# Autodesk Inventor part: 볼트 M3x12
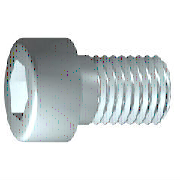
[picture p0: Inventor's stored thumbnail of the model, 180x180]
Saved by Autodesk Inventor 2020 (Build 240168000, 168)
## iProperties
Created: 2012-02
Part Number: 볼트 M3x12
Material: 강철, 연강
Description: 6각머리 태핑 나사
Document SubType Name: Modeling
Standard: KS B 1003
Designer: mduedu
Standards Organization: KS
Language: ko-KR
Size Designation: M 3 x 12
Categories: <MemberInstance><Categories><Category DisplayName="조임쇠" InternalName="e4da775c-781d-43d5-af7c-5136215cf5a6" Mnemonic="FSTN"><Category DisplayName="볼트" InternalN
Density: 1 g/cm^3
Appearance: 강철
IsCustomPart: 0
Author: mduedu
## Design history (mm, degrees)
sketch "스케치1"
  geometry: L1 (-0.867, 0)-(12, 0); L2 (12, 0)-(12, 1.5); L3 (12, 1.5)-(1.25, 1.5); L4 (1.25, 1.5)-(0.943, 1.5); L5 (0.943, 1.5)-(0, 1.5); L6 (0, 1.5)-(0, 2.75); L7 (0, 2.75)-(-3, 2.75); L8 (-3, 2.75)-(-3, 1.443); L9 (-3, 1.443)-(-1.7, 1.443); L10 (-1.7, 1.443)-(-0.867, 0); L11 (-6, 0)-(15, 0) reference; L12 (0, -0.55)-(0, 3.3) reference; L13 (1.25, 1.5)-(0, 1.5)
  constraints: 22 end point, 6 parallel, 2 collinear, 2 perpendicular, 1 horizontal, 1 point on line
  dimensions: "d1" = 10.75 distance from line of L3.end L2 (= GEL); "d2" = 0.30683 distance of L4.end L3.end (computed from GAL); "d3" = 3 distance between parallel lines of L8 L6 (= KOH); "d4" = 1.3 distance of L8.end L9.end (= INTI); "d5" = 60 deg angle of L10 L1; "d6" = 3 diameter of L3 L1 (= GD); "d7" = 3 diameter of L5 L1 (= BDM); "d8" = 2.88675 diameter of L9 L1 (= 1.1547 x SW); "d9" = 5.5 diameter of L7 L1 (= KOD); "d26" = 12 distance between parallel lines of L12 L2 (= NLG)
revolve "본체" sketch "스케치1" stored, may be unused: angle "d10" = 90 deg
sketch "스케치2"
  geometry: L1 (0, -3.85)-(0, 3.85) reference; L2 (-3.85, 0)-(3.85, 0) reference; L3 (1.443, 0)-(0.722, -1.25); L4 (0.722, -1.25)-(-0.722, -1.25); L5 (-0.722, -1.25)-(-1.443, 0); L6 (-1.443, 0)-(-0.722, 1.25); L7 (-0.722, 1.25)-(0.722, 1.25); L8 (0.722, 1.25)-(1.443, 0); 2 further points
  constraints: 12 end point, 1 coincident, 1 horizontal alignment, 1 point on line, 12 other
extrude "슬롯" join sketch "스케치2" stored distance "d11" = 10; taper "d12" = 0 deg
workplane "Work Plane1"
fillet "Fillet2" dims "d30" = 0.1 (= R)
body "Solid1"
fillet "모깎기1" dims "d17" = 0.3 (= RR)
feature "스레드" dims "d13" = 10.75 (= GEL), "d14" = 0
chamfer "모따기1" distance "d15" = 0.30673 (= -0.5 x SPD + 0.5 x GD); stored, may be unused: second distance "d16" = 0.30673 (= GUL), angle "d27" = 45 deg
other parameters: "GD" = 3 (= NND) [user parameter; used in 2 equation terms], "NLG" = 12 [user parameter; used in 1 equation term], "GEL" = 10.75 [user parameter; used in 2 equation terms], "KOD" = 5.5 [user parameter; used in 1 equation term], "KOH" = 3 [user parameter; used in 1 equation term], "INTI" = 1.3 [user parameter; used in 1 equation term], "GAL" = 0.30673 (= 0.61345 x PTC) [user parameter; used in 1 equation term], "GUL" = 0.30673 (= 0.61345 x PTC) [user parameter; used in 1 equation term], "BDM" = 3 (= NND) [user parameter; used in 1 equation term], "SW" = 2.5 [user parameter; used in 2 equation terms], "RR" = 0.3 [user parameter; used in 1 equation term], "SPD" = 2.38655 (= NND - 1.2269 x PTC) [user parameter; used in 1 equation term], "d19" = 0, "d28" = 0, "d29" = 0, "R" = 0.1 [user parameter; used in 1 equation term], "PHH" = 0.1 [user parameter], "GD1" = 2.38655 (= THREADDIA - 1.2269 x PTC) [user parameter], "THREADDIA" = 3 [user parameter; used in 1 equation term], "FAWI" = 45 deg [user parameter], "PTC" = 0.5 [user parameter; used in 5 equation terms], "NND" = 3 [user parameter; used in 3 equation terms], "TOA" = 30 deg [user parameter], "E0" = 2.8875 (= 1.155 x SW) [user parameter]
